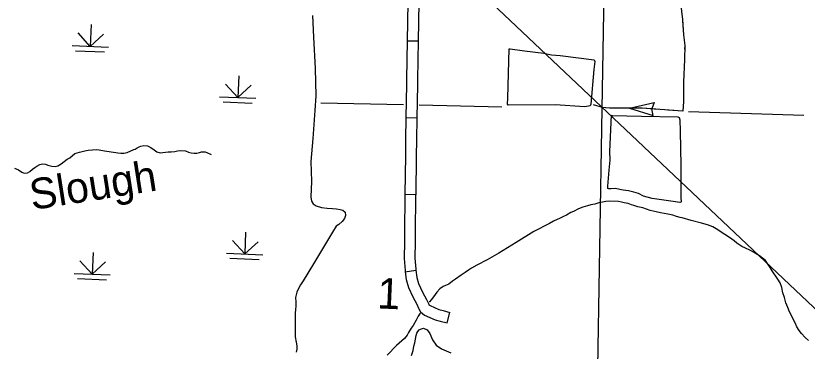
# Model space of a CAD drawing. Extents: x 1196286 to 1268366, y 2040822 to 2082115.
# Drawn here: x 1235560 to 1239648, y 2051997 to 2053727 of the extents above; entities that cross this region are included whole.
import ezdxf

# ---------------------------------------------------------------- set-up
doc = ezdxf.new("R2010")
doc.units = 0
for name, color, linetype in [('60', 7, 'Continuous'), ('62', 7, 'Continuous'), ('63', 7, 'Continuous'), ('Level 69', 7, 'Continuous'), ('Level 73', 7, 'Continuous'), ('Level 74', 7, 'Continuous'), ('Level 8', 7, 'Continuous'), ('Level 86', 7, 'Continuous')]:
    doc.layers.add(name, color=color, linetype=linetype)

msp = doc.modelspace()

# ---------------------------------------------------------------- linework, layer by layer
at = {"layer": '62'}
for points in [[(1238372, 2053521.8), (1238546.7, 2053500.3), (1238547.8, 2053499.8), (1238550.2, 2053491.3), (1238546.5, 2053450.3), (1238530, 2053270.9), (1238527.4, 2053263.1), (1238499.6, 2053258.4), (1238346.2, 2053267.1), (1238103.2, 2053266.8), (1238099.8, 2053271.6), (1238102.1, 2053301.8), (1238108.2, 2053556.6), (1238108.2, 2053557.5), (1238114.4, 2053557), (1238187.5, 2053546.5), (1238287.8, 2053534.3), (1238327.2, 2053526.4), (1238372.2, 2053521.8)], [(1238628.9, 2053027.6), (1238636.6, 2053213.8), (1238641, 2053213.1), (1238791.6, 2053210.1), (1238979.4, 2053205.2), (1238982.8, 2053204.2), (1238986, 2053202.2), (1238989.5, 2053191.1), (1238991.6, 2053132.6), (1238995.6, 2052955.2), (1238995.3, 2052784.6), (1238996.8, 2052772), (1238996.3, 2052767.1), (1238995.6, 2052766.1), (1238989.8, 2052764.5), (1238956.4, 2052769.3), (1238847.9, 2052784.6), (1238802.1, 2052797.1), (1238776.5, 2052810), (1238752, 2052816.8), (1238724.3, 2052824.7), (1238698.1, 2052827.9), (1238656.8, 2052836.5), (1238635, 2052834.2), (1238622.6, 2052835.1), (1238618.7, 2052836.2), (1238618.6, 2052836.4), (1238617.5, 2052848.3), (1238624.6, 2052930.6), (1238629.4, 2052981.5), (1238628.9, 2053028.2)], [(1235553.5, 2052941.1), (1235574.3, 2052932.8), (1235590.9, 2052920.4), (1235604, 2052916), (1235620.5, 2052917.6), (1235632.6, 2052924.5), (1235646.3, 2052935.1), (1235658.5, 2052944.2), (1235668.8, 2052951.9), (1235684.3, 2052960.3), (1235698.6, 2052963.4), (1235713.2, 2052961.2), (1235725.5, 2052957.2), (1235746.3, 2052951.9), (1235763.5, 2052948.9), (1235777.8, 2052952.8), (1235794.9, 2052963.3), (1235810.1, 2052975.1), (1235825.8, 2052988.3), (1235839.8, 2052994.8), (1235865.3, 2053016.5), (1235889.1, 2053023.9), (1235916.9, 2053030.8), (1235933.5, 2053033.2), (1235956.8, 2053036.4), (1235977.4, 2053037.5), (1235991.2, 2053035), (1236018.5, 2053030.7), (1236076.8, 2053021.2), (1236087.6, 2053019.5), (1236102.2, 2053018.5), (1236118.3, 2053018.9), (1236135.3, 2053022.7), (1236170, 2053036.7), (1236176.5, 2053039.6), (1236186.7, 2053045.7), (1236198.1, 2053051.5), (1236205.6, 2053054.4), (1236220.7, 2053057.5), (1236240.9, 2053055.6), (1236257.2, 2053047.7), (1236274.2, 2053035.7), (1236289, 2053025.3), (1236305.4, 2053019.7), (1236347.1, 2053026), (1236363.2, 2053026), (1236381.2, 2053027.9), (1236395.2, 2053030.7), (1236412.8, 2053031.4), (1236436, 2053030.2), (1236452.7, 2053024.2), (1236466.5, 2053019.8), (1236482.2, 2053017.6), (1236495.4, 2053019.2), (1236508.9, 2053022.4), (1236519.1, 2053024.8), (1236531.1, 2053025.7), (1236538.2, 2053024.8), (1236546.4, 2053022.7), (1236569.4, 2053012.1)], [(1239654.4, 2052050.8), (1239637.5, 2052067.7), (1239618.8, 2052087.3), (1239606.7, 2052104), (1239594, 2052122.4), (1239585.4, 2052142.8), (1239557.3, 2052199.1), (1239547.2, 2052222.2), (1239538, 2052246.9), (1239530.3, 2052273.4), (1239522.1, 2052298), (1239516.6, 2052324.4), (1239507.8, 2052348.7), (1239495.4, 2052368.8), (1239467, 2052411.9), (1239457.2, 2052429), (1239443.4, 2052448.9), (1239432.5, 2052464.2), (1239417.7, 2052476.5), (1239401.1, 2052488.9), (1239371.1, 2052506.8), (1239351.8, 2052517.3), (1239329.5, 2052528.7), (1239310.2, 2052537.3), (1239295.4, 2052546.3), (1239284.7, 2052554.4), (1239270.7, 2052566.3), (1239258.1, 2052575.2), (1239242.2, 2052586.1), (1239222.6, 2052598.9), (1239177.1, 2052628.8), (1239159.7, 2052638.9), (1239132.5, 2052649.2), (1239102.3, 2052657.4), (1239049, 2052670.8), (1239002.1, 2052684.6), (1238991.6, 2052687), (1238973.4, 2052692.3), (1238954, 2052698.3), (1238927.9, 2052703.7), (1238889.8, 2052710.1), (1238867, 2052715.5), (1238837.5, 2052722.9), (1238798.8, 2052736), (1238772.3, 2052741.8), (1238752.2, 2052748.6), (1238740.3, 2052752.3), (1238722.8, 2052758.6), (1238702.3, 2052762.8), (1238688.8, 2052765.7), (1238672.8, 2052769.4), (1238627.9, 2052771.4), (1238608, 2052769.2), (1238589.9, 2052765.4), (1238571.9, 2052762.8), (1238550.4, 2052756.1), (1238530, 2052751.2), (1238512.7, 2052747.1), (1238488.2, 2052740), (1238465.9, 2052731.1), (1238441.3, 2052718)], [(1238441.3, 2052718), (1238427.3, 2052711.9), (1238404.9, 2052698.8), (1238389.8, 2052692), (1238372, 2052683.7), (1238338.3, 2052666.7), (1238316, 2052656.2), (1238235.7, 2052614.2), (1238145.4, 2052558.1), (1238055.9, 2052502.7), (1237994.5, 2052467.4), (1237941.1, 2052440.3), (1237914.5, 2052424.6), (1237898.6, 2052414.1), (1237880.4, 2052402), (1237859.9, 2052388.1), (1237831.4, 2052368.4), (1237816.5, 2052357.4), (1237796.4, 2052342.4), (1237780.5, 2052335.2), (1237768.4, 2052330.1), (1237750.2, 2052318.1), (1237734.5, 2052301.1), (1237727.1, 2052289.2), (1237717.5, 2052276.6), (1237706, 2052262.2), (1237697.1, 2052251.5), (1237696.1, 2052250.6)], [(1237648.2, 2052193.1), (1237644.9, 2052187), (1237638.3, 2052177.4), (1237628.5, 2052156.5), (1237611.9, 2052129), (1237603, 2052115.7), (1237589.1, 2052092.6), (1237582, 2052079.6), (1237567.8, 2052062.2), (1237554.8, 2052049.3), (1237526.3, 2052025.8), (1237479.2, 2051975.2)]]:
    msp.add_lwpolyline(points, dxfattribs=at)
at = {"layer": '63'}
for p, q in [((1238730.4, 2053250.5), (1238856.9, 2053279.5)), ((1238856.9, 2053279.5), (1238845.8, 2053247.1)), ((1238730.4, 2053250.5), (1238852.3, 2053213)), ((1238852.3, 2053213), (1238845.7, 2053246.6))]:
    msp.add_line(p, q, dxfattribs=at)
for points in [[(1239300.2, 2055162), (1239268, 2054667.3), (1239263.6, 2054600), (1239254.3, 2054566), (1239242.9, 2054535), (1239183.8, 2054411.7), (1239088.3, 2054185.2), (1239057.6, 2054092.6), (1239040.4, 2054019.9), (1239020.7, 2053951.1), (1239006.9, 2053896.1), (1238999.1, 2053842.8), (1238992.9, 2053793.7), (1239003.5, 2053708.5), (1239009.8, 2053629), (1239015.5, 2053573.6), (1239013.3, 2053501.4), (1239009.1, 2053385.2), (1239008.3, 2053284.4), (1239005.1, 2053236), (1238794.7, 2053250.3), (1238627.2, 2053250.7), (1238589.8, 2053253.3), (1238544, 2053267.4)], [(1239300.2, 2055162), (1239268, 2054667.3), (1239263.6, 2054600), (1239254.3, 2054566), (1239242.9, 2054535), (1239183.8, 2054411.7), (1239088.3, 2054185.2), (1239057.6, 2054092.6), (1239040.4, 2054019.9), (1239020.7, 2053951.1), (1239006.9, 2053896.1), (1238999.1, 2053842.8), (1238992.9, 2053793.7), (1239003.5, 2053708.5), (1239009.8, 2053629), (1239015.5, 2053573.6), (1239013.3, 2053501.4), (1239009.1, 2053385.2), (1239008.3, 2053284.4), (1239005.1, 2053236), (1238794.7, 2053250.3), (1238627.2, 2053250.7), (1238589.8, 2053253.3), (1238544, 2053267.4)], [(1239004, 2053702.6), (1239009.8, 2053629), (1239015.5, 2053573.6), (1239014.9, 2053554.6)], [(1239013.4, 2053505.1), (1239013.3, 2053501.4), (1239009.1, 2053385.2), (1239008.9, 2053356.7)], [(1239008.5, 2053307.2), (1239008.3, 2053284.4), (1239005.1, 2053236), (1238928.1, 2053241.2)], [(1238606.7, 2053252.1), (1238589.8, 2053253.3), (1238544, 2053267.4)], [(1238680.9, 2053250.6), (1238627.2, 2053250.7), (1238606.7, 2053252.1)], [(1238878.7, 2053244.6), (1238794.7, 2053250.3), (1238750.1, 2053250.4)]]:
    msp.add_lwpolyline(points, dxfattribs=at)
at = {"layer": 'Level 69'}
for p, q in [((1237581.8, 2053598.4), (1237638.1, 2053597.4)), ((1237575.3, 2053202.4), (1237631.5, 2053201.5)), ((1237569.4, 2052806.4), (1237625.6, 2052805.6)), ((1237571.4, 2052406.3), (1237627.1, 2052414.2))]:
    msp.add_line(p, q, dxfattribs=at)
for points in [[(1237585.2, 2053796.3), (1237581.8, 2053598.4)], [(1237641.5, 2053795.4), (1237638.1, 2053597.4)], [(1237581.8, 2053598.4), (1237578.4, 2053400.4)], [(1237638.1, 2053597.4), (1237634.7, 2053399.4)], [(1237578.4, 2053400.4), (1237578, 2053372.8), (1237575.3, 2053202.4)], [(1237634.7, 2053399.4), (1237634.2, 2053371.9), (1237631.5, 2053201.5)], [(1237575.3, 2053202.4), (1237573.5, 2053088.1), (1237572.2, 2053004.4)], [(1237631.5, 2053201.5), (1237629.7, 2053087.3), (1237628.5, 2053003.5)], [(1237572.2, 2053004.4), (1237569.4, 2052806.4)], [(1237628.5, 2053003.5), (1237625.6, 2052805.6)], [(1237569.4, 2052806.4), (1237569.3, 2052801.1), (1237567.6, 2052608.2)], [(1237625.6, 2052805.6), (1237625.5, 2052800.4), (1237623.8, 2052607.7)], [(1237567.6, 2052608.2), (1237567.2, 2052562.4), (1237565.5, 2052475), (1237570.5, 2052412.9), (1237571.4, 2052406.3)], [(1237623.8, 2052607.7), (1237623.4, 2052561.5), (1237621.8, 2052476.7), (1237626.4, 2052419), (1237627.1, 2052414.2)], [(1237571.4, 2052406.3), (1237577.1, 2052365.8), (1237588, 2052325.7), (1237611.3, 2052276.5), (1237631.4, 2052238.8), (1237640.1, 2052219.3), (1237642.4, 2052214.3)], [(1237627.1, 2052414.2), (1237632.3, 2052377.1), (1237640.9, 2052345.3), (1237661.5, 2052301.8), (1237681.9, 2052263.5), (1237691.2, 2052242.8), (1237693.3, 2052238.4)], [(1237642.4, 2052214.3), (1237649.7, 2052198.8), (1237671.2, 2052183.2), (1237699.3, 2052170.5), (1237726.1, 2052159.1), (1237751.9, 2052151.6), (1237787.6, 2052142.2)], [(1237693.3, 2052238.4), (1237694.4, 2052235.9), (1237699.6, 2052232.1), (1237722, 2052222), (1237745, 2052212.1), (1237766.9, 2052205.8), (1237802, 2052196.6)], [(1237787.6, 2052142.2), (1237802, 2052196.6)]]:
    msp.add_lwpolyline(points, dxfattribs=at)
at = {"layer": 'Level 73'}
for p, q in [((1235949.7, 2053682.1), (1235944.9, 2053569.7)), ((1235944.9, 2053569.7), (1235881.5, 2053638.8)), ((1235944.9, 2053569.7), (1236014, 2053633.1)), ((1235851.3, 2053573.8), (1236038.6, 2053565.7)), ((1235868.9, 2053547.4), (1236018.8, 2053541)), ((1236711.4, 2053418.2), (1236706.6, 2053305.8)), ((1236706.6, 2053305.8), (1236643.2, 2053374.8)), ((1236706.6, 2053305.8), (1236775.7, 2053369.2)), ((1236613, 2053309.8), (1236800.3, 2053301.8)), ((1236630.6, 2053283.4), (1236780.5, 2053277)), ((1236747.3, 2052610.6), (1236742.5, 2052498.2)), ((1236742.5, 2052498.2), (1236679.1, 2052567.3)), ((1236742.5, 2052498.2), (1236811.6, 2052561.6)), ((1235959.6, 2052506.6), (1235954.7, 2052394.2)), ((1236648.9, 2052502.3), (1236836.2, 2052494.2)), ((1235954.7, 2052394.2), (1235891.3, 2052463.2)), ((1235954.7, 2052394.2), (1236023.8, 2052457.6)), ((1236666.5, 2052475.9), (1236816.4, 2052469.5)), ((1235861.1, 2052398.2), (1236048.4, 2052390.2)), ((1235878.7, 2052371.9), (1236028.6, 2052365.4))]:
    msp.add_line(p, q, dxfattribs=at)
at = {"layer": 'Level 74'}
for points in [[(1237092.2, 2053728.8), (1237097.8, 2053616.9), (1237105.9, 2053455), (1237110.2, 2053314.6), (1237104.2, 2053238.4), (1237094.3, 2053094.1), (1237083.3, 2052975.8), (1237086.9, 2052872.3), (1237084.2, 2052792.3), (1237088.2, 2052771.1), (1237096.6, 2052756.7), (1237111.4, 2052746.2), (1237139.3, 2052737.4), (1237168.5, 2052734.1), (1237195.4, 2052732.5), (1237217.5, 2052731.7), (1237236.2, 2052728.3), (1237249.6, 2052723.9), (1237261.8, 2052713.8), (1237262.9, 2052697.3), (1237257.4, 2052680.5), (1237245.8, 2052665.6), (1237227.9, 2052650.9), (1237215, 2052641.1), (1237196, 2052611.3), (1237097.2, 2052446.7), (1237044.1, 2052359.7), (1237029.9, 2052339.3), (1237017.8, 2052315.9), (1237011.5, 2052301.7), (1237005.3, 2052273.2), (1237006.4, 2052249.9), (1237005.9, 2052226.6), (1237005.7, 2052213.8), (1237003, 2052191.3), (1237003.7, 2052096.8), (1237002.4, 2052069.8), (1237008.3, 2052042.2)], [(1237603.9, 2051973.5), (1237612, 2052000.8), (1237616.9, 2052021.7), (1237621, 2052040.1), (1237624.7, 2052058.4), (1237628.5, 2052076.8), (1237632.1, 2052089.5), (1237636, 2052097.7), (1237644, 2052106.2), (1237650.9, 2052110.9), (1237665.2, 2052114.8), (1237685.3, 2052106.9), (1237698, 2052087), (1237713.1, 2052055.1), (1237730.6, 2052028.1), (1237759.1, 2052009.1), (1237806.6, 2051987.4)], [(1237008.3, 2052042.2), (1237011.3, 2052024.8), (1237012.1, 2052006.8), (1237009.1, 2051990.7)]]:
    msp.add_lwpolyline(points, dxfattribs=at)
at = {"layer": 'Level 8'}
msp.add_line((1243668.8, 2048450.6), (1232402.8, 2059105.7), dxfattribs=at)
at = {"layer": 'Level 86'}
for points in [[(1238553.7, 2050935.3), (1238553.1, 2051090.4), (1238588.2, 2053246.6), (1238599.5, 2053846.2)], [(1237135.4, 2053278.8), (1237562.4, 2053269.3)], [(1237643.5, 2053267.5), (1238070.2, 2053258.1)], [(1239035.1, 2053233.2), (1239630.3, 2053215.4)]]:
    msp.add_lwpolyline(points, dxfattribs=at)

# ---------------------------------------------------------------- texts
at = {"layer": '60'}
msp.add_text('1', height=158.4, rotation=357.548, dxfattribs=at).set_placement((1237425.2, 2052217.6))
at = {"layer": '62'}
msp.add_text('Slough', height=158.4, rotation=8.9245, dxfattribs=at).set_placement((1235644.6, 2052724.6))

doc.saveas('drawing.dxf')
